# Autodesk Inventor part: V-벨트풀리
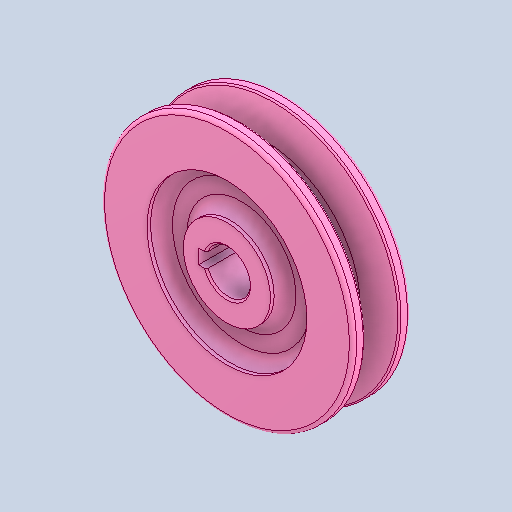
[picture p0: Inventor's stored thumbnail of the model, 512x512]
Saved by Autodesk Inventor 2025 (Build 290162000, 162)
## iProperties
Created: 2025-08
Part Number: V-벨트풀리
Material: 강철, 연강
Document SubType Name: Modeling
Designer: infra04
Density: 7.86 g/cm^3
Appearance: 기본값
Author: jhkim
Sending System: Autodesk Inventor 2026
Preprocessor: ST-DEVELOPER v20.1
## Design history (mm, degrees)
feature "Solid1"
node "솔리드1"
